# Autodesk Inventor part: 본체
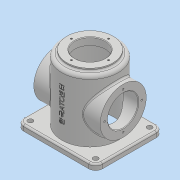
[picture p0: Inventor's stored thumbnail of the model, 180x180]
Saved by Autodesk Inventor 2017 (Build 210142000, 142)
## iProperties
Part Number: 본체
Material: 일반
Document SubType Name: Modeling
Designer: MRC
Density: 1 g/cm^3
Appearance: 기본값
Author: MRC
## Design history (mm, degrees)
sketch "스케치1"
  geometry: L1 (-70, -60)-(70, -60); L2 (70, -60)-(70, 60); L3 (70, 60)-(-70, 60); L4 (-70, 60)-(-70, -60); L5 (-70, -60)-(70, 60); L6 (70, -60)-(-70, 60); 1 further point
  constraints: 12 end point, 2 midpoint, 2 parallel, 1 horizontal, 1 perpendicular
  dimensions: "d0" = 140 distance of L3.end L2.end; "d1" = 120 distance of L2.end L1.end
extrude "돌출1" new body sketch "스케치1" distance "d2" = 10; taper "d3" = 0 deg
sketch "스케치2"
  geometry: C1 r 50 at (0, 0); 1 further point
  constraints: 1 centre point, 1 coincident
  dimensions: "d4" = 100 diameter of C1
extrude "돌출2" join sketch "스케치2" distance "d5" = 110; taper "d6" = 0 deg
sketch "스케치3"
  geometry: C1 r 50 at (0, 0) reference; C2 r 41 at (0, 0)
  constraints: 1 centre point, 1 coincident
  dimensions: "d7" = 82 diameter of C2
extrude "돌출3" join sketch "스케치3" distance "d8" = 5; taper "d9" = 0 deg
node "작업 평면1"
sketch "스케치4"
  geometry: L1 (-60, 0)-(60, 0) reference; C1 r 41 at (0, 60); 2 further points
  constraints: 1 centre point, 1 midpoint, 1 vertical alignment
  dimensions: "d11" = 60 distance from line of L1 C1.centre; "d12" = 82 diameter of C1
extrude "돌출4" join sketch "스케치4" stored distance "d13" = 5; taper "d14" = 0 deg
sketch "스케치5"
  geometry: C1 r 41 at (0, 0) reference; C2 r 27 at (0, 0); 1 further point
  constraints: 1 centre point, 1 coincident
  dimensions: "d15" = 54 diameter of C2
extrude "돌출5" cut sketch "스케치5" distance "d16" = 168; taper "d17" = 0 deg
sketch "스케치6"
  geometry: C1 r 27 at (0, 0) reference; 2 further points
  constraints: 1 vertical alignment
  dimensions: "d18" = 33 distance of C1.centre point (0, 33)
hole "구멍1" sketch "스케치6" at (0, 33) diameter "d19" = 3.242; stored, may be unused: countersink angle "d23" = 90 deg, drill point angle "d25" = 118 deg; dims "d20" = 8, "d21" = 4, "d22" = 2, "d24" = 10
sketch "스케치7"
  geometry: C1 r 42 at (0, 0); 1 further point
  constraints: 1 centre point, 1 coincident
  dimensions: "d29" = 84 diameter of C1
extrude "돌출6" cut sketch "스케치7" distance "d30" = 112; taper "d31" = 0 deg
sketch "스케치8"
  geometry: C1 r 41 at (0, 0) reference; C2 r 27 at (0, 0)
  constraints: 1 centre point, 1 coincident
  dimensions: "d32" = 54 diameter of C2
extrude "돌출7" cut sketch "스케치8" distance "d33" = 112; taper "d34" = 0 deg
sketch "스케치9"
  geometry: C1 r 27 at (0, 0) reference; 1 further point
  constraints: 1 vertical alignment
  dimensions: "d35" = 33 distance of C1.centre point (0, 33)
hole "구멍2" sketch "스케치9" at (0, 33) diameter "d36" = 3.242; stored, may be unused: countersink angle "d40" = 90 deg, drill point angle "d42" = 118 deg; dims "d37" = 8, "d38" = 4, "d39" = 2, "d41" = 10
fillet "모깎기1" dims "d46" = 12
fillet "모깎기2" dims "d47" = 6
fillet "모깎기3" dims "d48" = 3
chamfer "모따기1" distance "d49" = 1; stored, may be unused: second distance "d50" = 2, angle "d51" = 45 deg
sketch "스케치10"
  geometry: A1 r 9 centre (-58, -48) between (-67, -48) and (-58, -57) reference; A2 r 9 centre (58, -48) between (58, -57) and (67, -48) reference; A3 r 9 centre (58, 48) between (67, 48) and (58, 57) reference; A4 r 9 centre (-58, 48) between (-58, 57) and (-67, 48) reference
hole "구멍3" sketch "스케치10" at (-58, -48), (58, -48), (-58, 48), (58, 48) diameter "d52" = 9; stored, may be unused: countersink angle "d56" = 90 deg, drill point angle "d58" = 118 deg; dims "d53" = 8, "d54" = 4, "d55" = 2, "d57" = 10
node "작업 평면2"
sketch "스케치11"
  geometry: L1 (-58, -10)-(58, -10) reference; 3 further points
  constraints: 1 midpoint, 1 vertical alignment, 1 other
  dimensions: "d59" = 66 distance from line of L1 point (0, 56)
feature "엠보싱1" sketch "스케치11" dims "d0" = 140, "d1" = 120, "d60" = 0.5, "d61" = 0
node "솔리드1"
pattern_circular "원형 패턴1" dims angle "d27" = 360 deg
mirror "미러1"
pattern_circular "원형 패턴2" dims angle "d44" = 360 deg
other parameters: "d10" = 59
